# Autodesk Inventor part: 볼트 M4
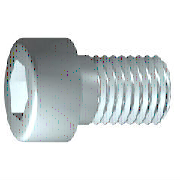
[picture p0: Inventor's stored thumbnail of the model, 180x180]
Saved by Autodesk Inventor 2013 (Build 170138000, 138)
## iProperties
IsCustomPart: 0
Created: 2012-02
Part Number: 볼트 M4
Material: 스테인리스강
Description: 6각 소켓 머리 캡 나사
Document SubType Name: Modeling
Standard: ISO 4762
Designer: mduedu
Standard Revision: Fourth edition 2004-03-01
Standards Organization: ISO
Language: ko-KR
Size Designation: M4 x 10
Categories: <MemberInstance><Categories><Category DisplayName="조임쇠" InternalName="e4da775c-781d-43d5-af7c-5136215cf5a6" Mnemonic="FSTN"><Category DisplayName="볼트" InternalN
Density: 8.08 g/cm^3
Author: mduedu
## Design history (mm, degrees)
sketch "스케치1"
  geometry: L1 (-1, 0)-(10, 0); L2 (10, 0)-(10, 2); L3 (10, 2)-(1.75, 2); L4 (1.75, 2)-(1.32, 2); L5 (1.32, 2)-(0, 2); L6 (0, 2)-(0, 3.5); L7 (0, 3.5)-(-4, 3.5); L8 (-4, 3.5)-(-4, 1.732); L9 (-4, 1.732)-(-2, 1.732); L10 (-2, 1.732)-(-1, 0); L11 (-6.8, 0)-(12.8, 0) reference; L12 (0, -0.7)-(0, 4.2) reference; L13 (1.75, 2)-(0, 2)
  constraints: 22 end point, 6 parallel, 2 collinear, 2 perpendicular, 1 horizontal, 1 point on line
  dimensions: "d1" = 8.25 distance from line of L3.end L2 (= GEL); "d2" = 0.42952 distance of L4.end L3.end (computed from GAL); "d3" = 4 distance between parallel lines of L8 L6 (= KOH); "d4" = 2 distance of L8.end L9.end (= INTI); "d5" = 60 deg angle of L10 L1; "d6" = 4 diameter of L3 L1 (= GD); "d7" = 4 diameter of L5 L1 (= BDM); "d8" = 3.4641 diameter of L9 L1 (= 1.1547 x SW); "d9" = 7 diameter of L7 L1 (= KOD); "d26" = 10 distance between parallel lines of L12 L2 (= NLG)
revolve "본체" sketch "스케치1" stored, may be unused: angle "d10" = 90 deg
sketch "스케치2"
  geometry: L1 (0, -4.9)-(0, 4.9) reference; L2 (-4.9, 0)-(4.9, 0) reference; L3 (1.732, 0)-(0.866, -1.5); L4 (0.866, -1.5)-(-0.866, -1.5); L5 (-0.866, -1.5)-(-1.732, 0); L6 (-1.732, 0)-(-0.866, 1.5); L7 (-0.866, 1.5)-(0.866, 1.5); L8 (0.866, 1.5)-(1.732, 0); 2 further points
  constraints: 12 end point, 1 coincident, 1 horizontal alignment, 1 point on line, 12 other
extrude "슬롯" join sketch "스케치2" stored distance "d11" = 10; taper "d12" = 0 deg
workplane "Work Plane1"
fillet "Fillet2" dims "d30" = 0.1 (= R)
body "Solid1"
fillet "모깎기1" dims "d17" = 0.4 (= RR)
feature "스레드" dims "d13" = 8.25 (= GEL), "d14" = 0
chamfer "모따기1" distance "d15" = 0.42941 (= -0.5 x SPD + 0.5 x GD); stored, may be unused: second distance "d16" = 0.42941 (= GUL), angle "d27" = 45 deg
other parameters: "GD" = 4 [user parameter; used in 2 equation terms], "NLG" = 10 [user parameter; used in 1 equation term], "GEL" = 8.25 [user parameter; used in 2 equation terms], "KOD" = 7 [user parameter; used in 1 equation term], "KOH" = 4 [user parameter; used in 1 equation term], "INTI" = 2 [user parameter; used in 1 equation term], "GAL" = 0.42941 (= 0.61345 x PTC) [user parameter; used in 1 equation term], "GUL" = 0.42941 (= 0.61345 x PTC) [user parameter; used in 1 equation term], "BDM" = 4 (= NND) [user parameter; used in 1 equation term], "SW" = 3 [user parameter; used in 2 equation terms], "RR" = 0.4 [user parameter; used in 1 equation term], "SPD" = 3.14117 (= NND - 1.2269 x PTC) [user parameter; used in 1 equation term], "d19" = 0, "d28" = 0, "d29" = 0, "R" = 0.1 [user parameter; used in 1 equation term], "TOA" = 30 deg [user parameter], "GD1" = 3.14117 (= THREADDIA - 1.2269 x PTC) [user parameter], "THREADDIA" = 4 [user parameter; used in 1 equation term], "FAWI" = 45 deg [user parameter], "TPU" = 14.28571 (computed from PTC) [user parameter], "PTC" = 0.7 [user parameter; used in 5 equation terms], "NND" = 4 [user parameter; used in 2 equation terms], "E0" = 3.465 (= 1.155 x SW) [user parameter]
